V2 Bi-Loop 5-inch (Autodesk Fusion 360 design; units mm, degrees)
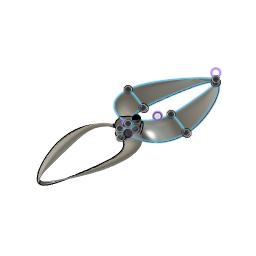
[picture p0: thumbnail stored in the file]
sketch "Hub 5mm Shaft" plane through (0, 0, 0) normal (0, 0, 1) x axis (1, 0, 0)
  circle C1 centre (0, 0) radius 6.5
  circle C2 centre (0, 0) radius 2.5
  point P1 (0, 0)
  point P2 (0, 0)
  point P3 (0, 0)
  coincident P1 P2
  coincident P1 P3
  dimension "d1" diameter C1 = 13
  dimension "d2" diameter C2 = 5
extrude "Extrude1" new body sketch "Hub 5mm Shaft" along normal blind 6 bodies "Hub 5mm Shaft"
sketch "Start Profile" plane through (0, 0, 0) normal (1, 0, 0) x axis (0, 1, 0)
  line L1 (-0.9, 0) -> (0, 0)
  line L2 (-5, 0) -> (-5.9, 0)
  curve K1 (-5, 0) -> (-5.9, 0)
  curve K2 (0, 0) -> (-0.9, 0)
  curve K3 (6.3, 6) -> (5.7, 6)
  curve K4 (0.3, 6) -> (-0.3, 6)
  curve K5 (-1, -1.5) -> (1, 1.5)
  curve K6 (-6, -1.5) -> (-4, 1.5)
  curve K7 (-4.9, 1.5) -> (-6.9, -1.5)
  curve K8 (0.1, 1.5) -> (-1.9, -1.5)
  point P1 (0, 0)
  point P2 (0, 0)
  point P6 (0, 0)
  point P3 (6, 6)
  point P4 (0, 6)
  point P8 (-5, 0)
  point P5 (-5.9, 0)
  point P7 (-0.9, 0)
  point P9 (5.7, 6)
  point P10 (6.3, 6)
  point P11 (-0.3, 6)
  point P12 (0.3, 6)
  point P21 (0, 0)
  point P24 (0, 0)
  coincident P1 P2
  coincident P1 P6
  horizontal L1
  horizontal L2
  midpoint P3 K3
  midpoint P4 K4
  midpoint P2 K5
  midpoint P8 K6
  midpoint P5 K7
  midpoint P7 K8
  dimension "d5" distance P2 P7 = 0.9
  dimension "d6" distance P5 P8 = 0.9
  dimension "d7" distance P2 P8 = 5
  dimension "d8" distance P4 P5 = 5.9
  dimension "d9" distance P2 P4 = 6
  dimension "d10" distance P2 P3 = 6
  dimension "d11" distance P2 P3 = 6
  dimension "d12" distance P9 P10 = 0.6
  dimension "d13" distance P11 P12 = 0.6
  dimension "d17" distance P21 = 63.5 (= "( 127 / 2 ) * 1 mm")
  dimension "d38" distance P24 = 21.1667 (= "( 127 / 3 / 2 ) * 1 mm")
  dimension "d46" distance P24 = 21.1667 (= "( 127 / 2 / 3 ) * 1 mm")
sketch "Edge Profile" plane through (0, 0, 0) normal (1, 0, 0) x axis (0, 1, 0)
  line L1 (62.7, 0) -> (63.5, 0)
  curve K1 (62.7, 0) -> (63.5, 0)
  curve K2 (63.5, 1) -> (63.5, -1)
  curve K3 (62.7, -1) -> (62.7, 1)
  curve K4 (62.8, 2) -> (63.3, 2)
  point P2 (63.5, 0)
  point P3 (62.7, 0)
  point P4 (63.05, 2)
  point P9 (0, 0)
  point P10 (63.3, 2)
  point P11 (62.8, 2)
  horizontal L1
  midpoint P2 K2
  midpoint P3 K3
  midpoint P4 K4
  dimension "d14" distance P2 P3 = 0.8
  dimension "d15" distance P2 P4 = 2
  dimension "d16" distance P2 P4 = 0.45
  dimension "d17" distance P2 P9 = 63.5 (= "( 127 / 2 ) * 1 mm")
  dimension "d18" distance P10 P11 = 0.5
sketch "Target Rail" plane through (0, 0, 0) normal (0, 0, 1) x axis (1, 0, 0)
  line L1 (0, -0.9) -> (0, 0)
  line L2 (0, 21.1667) -> (0, 0)
  line L3 (21.1667, 21.1667) -> (0, 21.1667)
  line L4 (-21.1667, 21.1667) -> (0, 21.1667)
  circle C1 centre (0, 0) radius 63.5
  point P1 (0, 0)
  point P2 (0, 0)
  point P5 (0, 0)
  point P6 (0, 21.1667)
  point P7 (21.1667, 21.1667)
  point P8 (-21.1667, 21.1667)
  coincident P1 P2
  coincident P1 P5
  parallel L1 L2
  perpendicular L2 L3
  perpendicular L2 L4
  dimension "d19" diameter C1 = 127
  dimension "d20" distance P5 P6 = 21.1667 (= "( ( 127 / 2 ) / 3 ) * 1 mm")
  dimension "d21" distance P6 P7 = 21.1667 (= "( ( 127 / 2 ) / 3 ) * 1 mm")
  dimension "d22" distance P6 P8 = 21.1667 (= "( 127 / 2 / 3 ) * 1 mm")
work_plane "WorkPlane1" AlongDistance 21.1667 (= "( 127 / 2 / 3 ) * 1 mm")
sketch "Mid Profile" plane through (0, 21.1667, 0) normal (0, 1, 0) x axis (1, 0, 0)
  curve K1 (20.2667, 0) -> (21.1667, 0)
  curve K2 (18.5, -2) -> (23.8333, 2)
  curve K3 (9.3667, -6) -> (9.9667, -6)
  curve K4 (23.1333, 2) -> (17.4, -2)
  line L1 (20.2667, 0) -> (21.1667, 0)
  line L2 (9.3667, -6) -> (9.9667, -6)
  line L3 (-10.5667, 0) -> (-9.6667, 0)
  curve K5 (-10.5667, 0) -> (-9.6667, 0)
  curve K6 (-12.3333, -2) -> (-7, 2)
  curve K7 (-21.4667, -6) -> (-20.8667, -6)
  curve K8 (-7.7, 2) -> (-13.4333, -2)
  point P2 (0, 0)
  point P5 (21.1667, 0)
  point P7 (9.6667, -6)
  point P3 (9.9667, -6)
  point P4 (9.3667, -6)
  point P14 (-21.1667, -6)
  point P17 (-9.6667, 0)
  point P13 (-20.8667, -6)
  point P18 (-21.4667, -6)
  point P19 (-10.5667, 0)
  point P8 (20.2667, 0)
  dimension "d38" distance P2 P5 = 21.1667 (= "( 127 / 3 / 2 ) * 1 mm")
  dimension "d39" distance P5 P7 = 11.5
  dimension "d40" distance P5 P7 = 6
  dimension "d41" distance P3 P4 = 0.6
  dimension "d42" distance P14 P17 = 11.5
  dimension "d43" distance P14 P17 = 6
  dimension "d44" distance P13 P18 = 0.6
  dimension "d46" distance P2 P14 = 21.1667 (= "( 127 / 2 / 3 ) * 1 mm")
  dimension "d47" distance P17 P19 = 0.9
  dimension "d84" distance P5 P8 = 0.9
sketch "End Profile" plane through (0, 0, 0) normal (1, 0, 0) x axis (0, 1, 0)
  line L1 (5, 0) -> (5.8, 0)
  curve K1 (0, 0) -> (0.8, 0)
  curve K2 (-0.2, 1.5) -> (1.8, -1.5)
  curve K3 (-6.25, 6) -> (-5.75, 6)
  curve K4 (1, -1.5) -> (-1, 1.5)
  line L2 (0.8, 0) -> (0, 0)
  curve K5 (5, 0) -> (5.8, 0)
  curve K6 (4.8, 1.5) -> (6.8, -1.5)
  curve K7 (-0.25, 6) -> (0.35, 6)
  curve K8 (6, -1.5) -> (4, 1.5)
  line L3 (-6.25, 6) -> (-5.75, 6)
  line L4 (-0.25, 6) -> (0.35, 6)
  point P2 (0, 0)
  point P11 (0.8, 0)
  point P14 (5, 0)
  point P20 (5.8, 0)
  point P5 (0, 0)
  point P6 (0, 6)
  point P12 (0, 0)
  point P18 (-6, 6)
  point P7 (-6.25, 6)
  point P23 (-5.75, 6)
  point P3 (0.35, 6)
  point P17 (-0.25, 6)
  dimension "d57" distance P2 P11 = 0.8
  dimension "d58" distance P14 P20 = 0.8
  dimension "d59" distance P5 P20 = 5.8
  dimension "d60" distance P6 P12 = 6
  dimension "d61" distance P6 P20 = 5.8
  dimension "d62" distance P11 P18 = 6.8
  dimension "d63" distance P2 P7 = 6
  dimension "d65" distance P7 P23 = 0.5
  dimension "d66" distance P3 P17 = 0.6
  dimension "d67" distance P6 P17 = 0.25
sketch "Lower Rails" plane through (0, 0, 0) normal (0, 0, 1) x axis (1, 0, 0)
  curve K1 (0, 5) -> (0, -0.9)
  curve K2 (0, 0) -> (0, 5.8)
  curve K3 (-9, 0) -> (9, 0)
  curve K4 (9, -1.1) -> (-9, -0.7)
  curve K5 (-3, 5.8) -> (3, 5.8)
  curve K6 (3, 5) -> (-3, 5)
  curve K7 (-9.8204, 31.1339) -> (-9.5129, 11.1995)
  curve K8 (-10.4129, 11.1995) -> (-10.7204, 31.1339)
  curve K9 (-2.5, 63.5) -> (2.5, 63.5)
  curve K10 (2.2, 62.7) -> (-2.2, 62.7)
  point P2 (0, -0.9)
  point P7 (0, -0.9)
  point P3 (21.1667, 21.1667)
  point P8 (21.1667, 21.1667)
  point P4 (0, 63.5)
  point P9 (0, 63.5)
  point P5 (-10.5667, 21.1667)
  point P10 (-10.5667, 21.1667)
  point P11 (0, 5.8)
  point P16 (0, 5.8)
  point P12 (-9.6667, 21.1667)
  point P17 (-9.6667, 21.1667)
  point P13 (0, 62.7)
  point P18 (0, 62.7)
  point P14 (20.2667, 21.1667)
  point P19 (20.2667, 21.1667)
  point P1 (0, 0)
  point P15 (0, 0)
  point P6 (0, 5)
  coincident P2 P7
  coincident P3 P8
  coincident P4 P9
  coincident P5 P10
  coincident P11 P16
  coincident P12 P17
  coincident P13 P18
  coincident P14 P19
  coincident P1 P15
  midpoint P15 K3
  midpoint P2 K4
  midpoint P11 K5
  midpoint P6 K6
  midpoint P12 K7
  midpoint P5 K8
  parallel K7 K8
  midpoint P4 K9
  midpoint P13 K10
work_plane "WorkPlane2" AlongDistance 6
sketch "Upper Rails" plane through (0, 0, 6) normal (0, 0, 1) x axis (1, 0, 0)
  curve K1 (0, 0) -> (0, 6)
  curve K2 (9.5, -0.3) -> (-9.5, 0.3)
  curve K3 (5, 6) -> (-5, 6)
  curve K4 (9.6059, 28.9686) -> (9.7274, 13.3647)
  curve K5 (-21.1859, 12.7509) -> (-21.1474, 29.5825)
  curve K6 (-2, 63.1) -> (2, 63.1)
  point P2 (0, 6)
  point P7 (0, 6)
  point P3 (9.6667, 21.1667)
  point P8 (9.6667, 21.1667)
  point P5 (-21.1667, 21.1667)
  point P10 (-21.1667, 21.1667)
  point P6 (0, 0)
  point P4 (0, 63.1)
  coincident P2 P7
  coincident P3 P8
  coincident P5 P10
  midpoint P6 K2
  midpoint P2 K3
  midpoint P3 K4
  midpoint P5 K5
  midpoint P4 K6
loft "Loft1" sketch "Start Profile" + "Mid Profile" + "Edge Profile" bodies "Template 1 5x2.5x2"
loft "Loft2" sketch "Edge Profile" + "Mid Profile" + "End Profile"
circular_pattern "C-Pattern1" TotalAngle 360 bodies "Template 2 5x2.5x2"
sketch "Blade Trimmer" plane through (0, 0, 0) normal (0, 0, 1) x axis (1, 0, 0)
  circle C1 centre (0, 0) radius 3
  point P1 (0, 0)
  point P2 (0, 0)
  coincident P1 P2
  dimension "d71" diameter C1 = 6
extrude "Extrude2" cut sketch "Blade Trimmer" along normal blind 14
copy_paste_bodies "CopyPasteBodies1"
chamfer "Start Profile" distance 0.5
offset_faces "OffsetFaces1" distance 2
combine "Start Profile"
fillet "Fillet1" radius 1
offset_faces "OffsetFaces2" distance -2
sketch "Fillet Trimmer" plane through (0, 0, 6) normal (0, 0, 1) x axis (-1, 0, 0)
  arc A1 centre (0, 0) radius 6.5 clockwise from (6.4969, 0.2006) to (5.6269, -3.2539)
  arc A2 centre (0, 0) radius 6.5 clockwise from (0.9587, 6.4289) to (5.2455, 3.8386)
  arc A3 centre (0, 0) radius 6.5 clockwise from (-6.4969, -0.2006) to (-5.6269, 3.2539)
  arc A4 centre (0, 0) radius 6.5 clockwise from (-5.2455, -3.8386) to (-6.4969, -0.2006)
  arc A5 centre (0, 0) radius 6.5 clockwise from (-0.9587, -6.4289) to (-5.2455, -3.8386)
  arc A6 centre (0, 0) radius 6.5 clockwise from (5.6269, -3.2539) to (-0.9587, -6.4289)
  circle C1 centre (0, 0) radius 3
  circle C2 centre (0, 0) radius 7.5
  arc A7 centre (0, 0) radius 6.5 clockwise from (5.2455, 3.8386) to (6.4969, 0.2006)
  arc A8 centre (0, 0) radius 6.5 clockwise from (-5.6269, 3.2539) to (0.9587, 6.4289)
  point P1 (0, 0)
  point P10 (0, 0)
  coincident P1 P10
  dimension "d79" diameter C2 = 15
extrude "Extrude3" cut sketch "Fillet Trimmer" profile of A1 A2 A3 A4 A5 A6 C1 C2 along normal blind 5
mirror "Mirror1" mirrorStitchTolerance 0.1 bodies "5x2.5x2 CW"
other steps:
base_feature "Base Feature" bodies "Hub 5mm Shaft", "5x2.5x2 CCW"
named bodies: "Hub 5mm Shaft", "Template 1 5x2.5x2", "Template 2 5x2.5x2", "5x2.5x2 CCW", "5x2.5x2 CW"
